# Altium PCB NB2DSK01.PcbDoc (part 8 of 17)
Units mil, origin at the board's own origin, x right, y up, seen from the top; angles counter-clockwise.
Board outline 11815 x 6500.03 mil, 8 copper layers (Top Layer, MidLayer1, MidLayer2, GND, PWR, MidLayer3, MidLayer4, Bottom Layer), stack 74.62 mil thick; 798 components, 1002 nets, 3927 pads, 3182 vias.
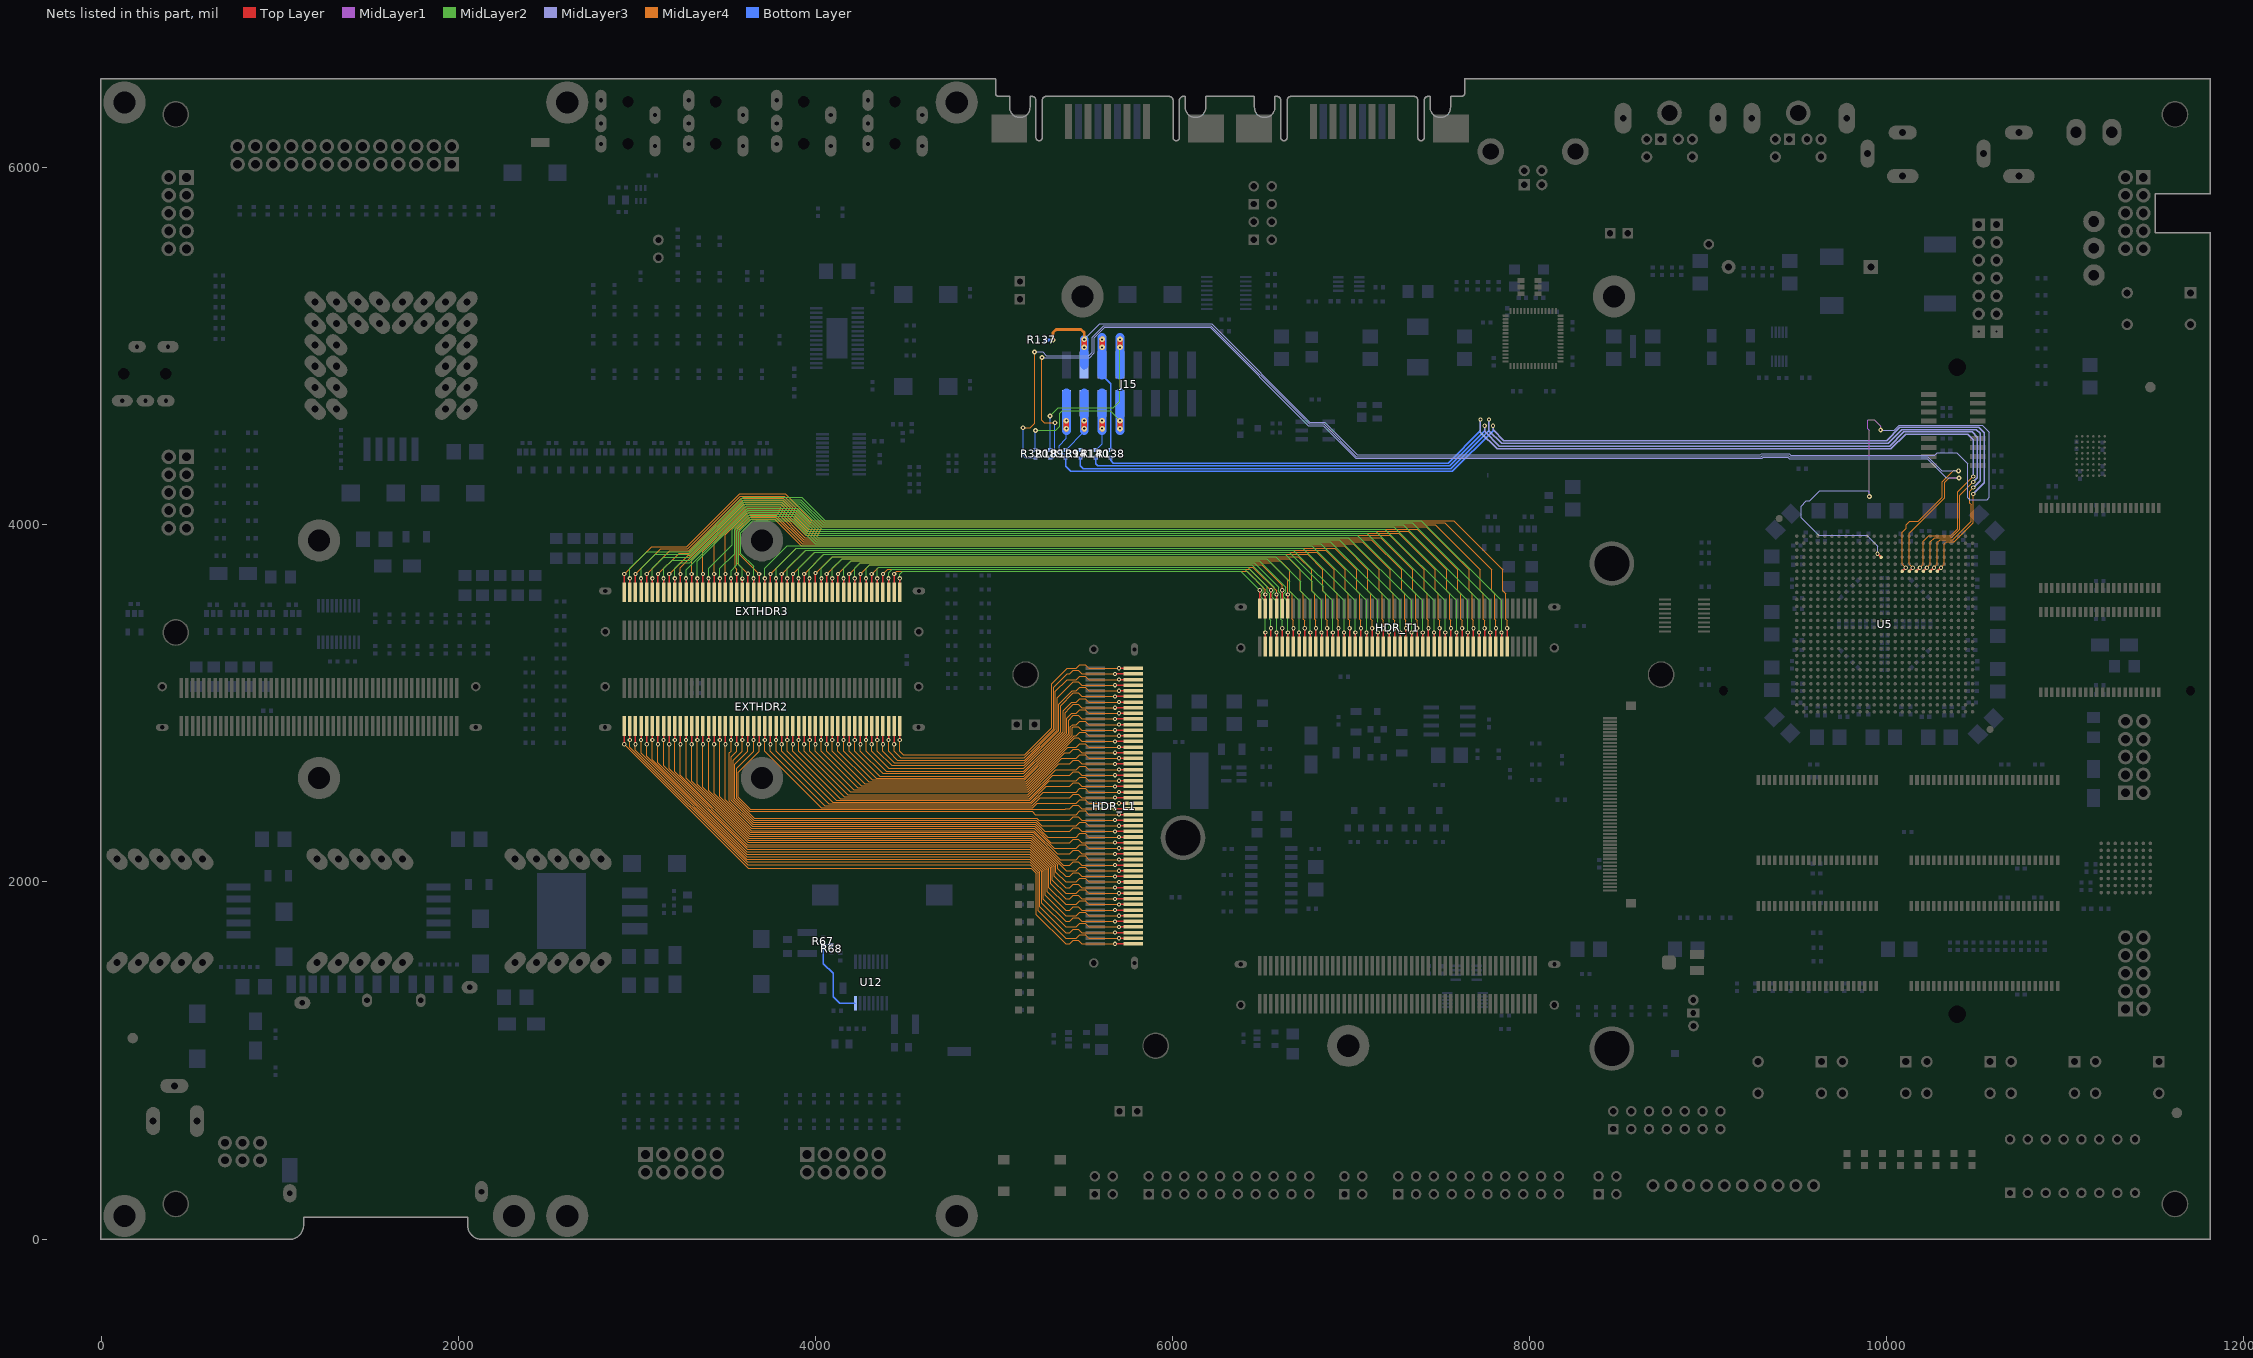
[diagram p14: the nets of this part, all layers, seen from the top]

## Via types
v1: diameter 23.62, hole 11.81, Top Layer to Bottom Layer, tented both sides, 1950 vias
v2: diameter 27.56, hole 11.81, Top Layer to Bottom Layer, tented both sides, 679 vias
v3: diameter 23.62, hole 11.81, Top Layer to Bottom Layer, 194 vias
v4: diameter 31.5, hole 11.81, Top Layer to Bottom Layer, tented both sides, 178 vias
v5: diameter 21.65, hole 11.81, Top Layer to Bottom Layer, tented both sides, 67 vias
v6: diameter 23.62, hole 11.81, Top Layer to Bottom Layer, tented bottom, 53 vias
v7: diameter 26, hole 11.81, Top Layer to Bottom Layer, tented both sides, 21 vias
v8: diameter 26, hole 11.81, Top Layer to Bottom Layer, 13 vias
v9: diameter 28, hole 11.81, Top Layer to Bottom Layer, 8 vias
v10: diameter 25.59, hole 11.81, Top Layer to Bottom Layer, tented both sides, 7 vias
v11: diameter 39.37, hole 11.81, Top Layer to Bottom Layer, tented both sides, 5 vias
v12: diameter 30, hole 11.81, Top Layer to Bottom Layer, 3 vias
v13: diameter 30, hole 11.81, Top Layer to Bottom Layer, tented both sides, 2 vias
v14: diameter 23, hole 11.81, Top Layer to Bottom Layer, tented both sides, 1 vias
v15: diameter 26.56, hole 11.81, Top Layer to Bottom Layer, tented both sides, 1 vias

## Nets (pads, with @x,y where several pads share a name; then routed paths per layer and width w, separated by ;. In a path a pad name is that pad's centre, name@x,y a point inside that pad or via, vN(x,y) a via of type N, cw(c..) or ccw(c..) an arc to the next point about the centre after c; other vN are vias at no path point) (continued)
EXT_B.D0: EXTHDR2.2 HDR_L1.2 | length 1820.1
  Top Layer w7.87: v1(4472.44,2795.28) EXTHDR2.2@4472.44,2874.02 ; v1(5700.79,3196.85) HDR_L1.2@5779.53,3196.85
  MidLayer4 w5: v1(4472.44,2795.28) 4472.44,2732.28 4493.27,2711.45 5172.08,2711.45 5323.67,2863.04 5323.67,3111.07 5409.45,3196.85 5460.63,3196.85 5480.32,3216.54 5511.81,3216.54 5531.5,3196.85 v1(5700.79,3196.85)
EXT_B.D1: EXTHDR2.4 HDR_L1.4 | length 1841.6
  Top Layer w7.87: v1(4440.95,2771.65) EXTHDR2.4@4440.95,2874.02 ; v1(5677.16,3165.36) HDR_L1.4@5779.53,3165.36
  MidLayer4 w5: v1(4440.95,2771.65) 4440.95,2732.28 4477.78,2695.45 5170.23,2695.45 5238.27,2763.5 5333.67,2858.89 5333.67,3089.57 5409.45,3165.35 5425.2,3165.35 5444.88,3185.04 5472.44,3185.04 5492.13,3165.36 v1(5677.16,3165.36)
EXT_B.D2: EXTHDR2.6 HDR_L1.6 | length 1860.7
  Top Layer w7.87: v1(4409.45,2795.28) EXTHDR2.6@4409.45,2874.02 ; v1(5700.79,3133.86) HDR_L1.6@5779.53,3133.86
  MidLayer4 w5: v1(4409.45,2795.28) 4409.45,2732.28 4459.28,2682.45 5171.37,2682.45 5343.67,2854.75 5343.67,3068.08 5409.45,3133.86 5460.63,3133.86 5480.32,3153.54 5511.81,3153.54 5531.5,3133.86 v1(5700.79,3133.86)
EXT_B.D3: EXTHDR2.8 HDR_L1.8 | length 1872.2
  Top Layer w7.87: v1(4377.95,2771.65) EXTHDR2.8@4377.95,2874.02 ; v1(5677.16,3102.36) HDR_L1.8@5779.53,3102.36
  MidLayer4 w5: v1(4377.95,2771.65) 4377.95,2732.28 4442.78,2667.45 5170.51,2667.45 5353.67,2850.61 5353.67,3030.83 5425.2,3102.36 5444.88,3122.05 5472.44,3122.05 5492.13,3102.36 v1(5677.16,3102.36)
EXT_B.D4: EXTHDR2.10 HDR_L1.10 | length 1884.8
  Top Layer w7.87: v1(4346.46,2795.28) EXTHDR2.10@4346.46,2874.02 ; v1(5700.79,3070.87) HDR_L1.10@5779.53,3070.87
  MidLayer4 w5: v1(4346.46,2795.28) 4346.46,2732.28 4426.29,2652.45 5169.65,2652.45 5268.27,2751.07 5363.67,2846.47 5363.67,2995.53 5439,3070.87 5460.63,3070.87 5480.32,3090.55 5511.81,3090.55 5531.5,3070.87 v1(5700.79,3070.87)
EXT_B.D5: EXTHDR2.12 HDR_L1.12 | length 1914.4
  Top Layer w7.87: v1(4314.96,2771.65) EXTHDR2.12@4314.96,2874.02 ; v1(5677.16,3039.37) HDR_L1.12@5779.53,3039.37
  MidLayer4 w5: v1(4314.96,2771.65) 4314.96,2732.28 4410.79,2636.45 5167.79,2636.45 5373.67,2842.33 5373.67,2987.84 5444.88,3059.06 5472.44,3059.06 5492.13,3039.37 v1(5677.16,3039.37)
EXT_B.D6: EXTHDR2.14 HDR_L1.14 | length 1929.6
  Top Layer w7.87: v1(4283.47,2795.28) EXTHDR2.14@4283.47,2874.02 ; v1(5700.79,3007.88) HDR_L1.14@5779.53,3007.88
  MidLayer4 w5: v1(4283.47,2795.28) 4283.47,2732.28 4395.3,2620.45 5165.94,2620.45 5387.81,2842.33 5387.81,2959.68 5436,3007.88 5460.63,3007.88 5480.32,3027.56 5511.81,3027.56 5531.5,3007.88 v1(5700.79,3007.88)
EXT_B.D7: EXTHDR2.16 HDR_L1.16 | length 1954.2
  Top Layer w7.87: v1(4251.97,2771.65) EXTHDR2.16@4251.97,2874.02 ; v1(5677.16,2976.38) HDR_L1.16@5779.53,2976.38
  MidLayer4 w5: v1(4251.97,2771.65) 4251.97,2732.28 4375.8,2608.45 5168.08,2608.45 5298.27,2738.64 5397.81,2838.18 5397.81,2948.99 5425.2,2976.38 5444.88,2996.06 5472.44,2996.06 5492.13,2976.38 v1(5677.16,2976.38)
EXT_B.D8: EXTHDR2.18 HDR_L1.18 | length 1969.2
  Top Layer w7.87: v1(4220.47,2795.28) EXTHDR2.18@4220.47,2874.02 ; v1(5700.79,2944.88) HDR_L1.18@5779.53,2944.88
  MidLayer4 w5: v1(4220.47,2795.28) 4220.47,2732.28 4359.3,2593.45 5167.22,2593.45 5407.81,2834.04 5407.81,2917.69 5435,2944.88 5460.63,2944.88 5480.32,2964.57 5511.81,2964.57 5531.5,2944.88 v1(5700.79,2944.88)
EXT_B.D9: EXTHDR2.20 HDR_L1.20 | length 1993.1
  Top Layer w7.87: v1(4188.98,2771.65) EXTHDR2.20@4188.98,2874.02 ; v1(5677.16,2913.39) HDR_L1.20@5779.53,2913.39
  MidLayer4 w5: v1(4188.98,2771.65) 4188.98,2732.28 4339.81,2581.45 5169.36,2581.45 5417.81,2829.9 5417.81,2906 5444.88,2933.07 5472.44,2933.07 5492.13,2913.39 v1(5677.16,2913.39)
EXT_B.D10: EXTHDR2.22 HDR_L1.22 | length 2000.4
  Top Layer w7.87: v1(4157.48,2795.28) EXTHDR2.22@4157.48,2874.02 ; v1(5700.79,2881.89) HDR_L1.22@5779.53,2881.89
  MidLayer4 w5: v1(4157.48,2795.28) 4157.48,2732.28 4318.31,2571.45 5173.51,2571.45 5328.27,2726.22 5427.81,2825.76 5427.81,2868.7 5441,2881.89 5460.63,2881.89 5480.32,2901.58 5511.81,2901.58 5531.5,2881.89 v1(5700.79,2881.89)
EXT_B.D11: EXTHDR2.24 HDR_L1.24 | length 2027.1
  Top Layer w7.87: v1(4125.99,2771.65) EXTHDR2.24@4125.98,2874.02 ; v1(5677.16,2850.4) HDR_L1.24@5779.53,2850.39
  MidLayer4 w5: v1(4125.99,2771.65) 4125.99,2732.28 4297.82,2560.45 5176.65,2560.45 5437.81,2821.62 5437.81,2863.01 5444.88,2870.08 5472.44,2870.08 5492.13,2850.4 v1(5677.16,2850.4)
EXT_B.D12: EXTHDR2.26 HDR_L1.26 | length 2030.4
  Top Layer w7.87: v1(4094.49,2795.28) EXTHDR2.26@4094.49,2874.02 ; v1(5700.79,2818.9) HDR_L1.26@5779.53,2818.9
  MidLayer4 w5: v1(4094.49,2795.28) 4094.49,2732.28 4277.32,2549.45 5179.79,2549.45 5348.27,2717.93 5449.23,2818.9 5460.63,2818.9 5480.32,2838.58 5511.81,2838.58 5531.5,2818.9 v1(5700.79,2818.9)
EXT_B.D13: EXTHDR2.28 HDR_L1.28 | length 2057.2
  Top Layer w7.87: v1(4062.99,2771.65) EXTHDR2.28@4062.99,2874.02 ; v1(5677.16,2787.4) HDR_L1.28@5779.53,2787.4
  MidLayer4 w5: v1(4062.99,2771.65) 4062.99,2732.28 4255.82,2539.45 5183.93,2539.45 5358.27,2713.79 ; 5358.27,2713.79 5451.57,2807.09 5472.44,2807.09 5492.13,2787.4 v1(5677.16,2787.4)
EXT_B.D14: EXTHDR2.30 HDR_L1.30 | length 2085.5
  Top Layer w7.87: v1(4031.5,2795.28) EXTHDR2.30@4031.5,2874.02 ; v1(5700.79,2755.91) HDR_L1.30@5779.53,2755.91
  MidLayer4 w5: v1(4031.5,2795.28) 4031.5,2732.28 4236.33,2527.45 5186.07,2527.45 5414.53,2755.91 5460.63,2755.91 5480.32,2775.59 5511.81,2775.59 5531.5,2755.91 v1(5700.79,2755.91)
EXT_B.D15: EXTHDR2.32 HDR_L1.32 | length 2113.1
  Top Layer w7.87: v1(4000,2771.65) EXTHDR2.32@4000,2874.02 ; v1(5677.16,2724.41) HDR_L1.32@5779.53,2724.41
  MidLayer4 w5: v1(4000,2771.65) 4000,2732.28 4215.83,2516.45 5189.22,2516.45 5397.17,2724.41 5425.2,2724.41 5444.88,2744.1 5472.44,2744.1 5492.13,2724.41 v1(5677.16,2724.41)
EXT_B.D16: EXTHDR2.34 HDR_L1.34 | length 2141.5
  Top Layer w7.87: v1(3968.51,2795.28) EXTHDR2.34@3968.5,2874.02 ; v1(5700.79,2692.91) HDR_L1.34@5779.53,2692.91
  MidLayer4 w5: v1(3968.51,2795.28) 3968.51,2732.28 4196.33,2504.45 5191.36,2504.45 5379.82,2692.91 5460.63,2692.91 5480.32,2712.6 5511.81,2712.6 5531.5,2692.91 v1(5700.79,2692.91)
EXT_B.D17: EXTHDR2.36 HDR_L1.36 | length 2174
  Top Layer w7.87: v1(3937.01,2771.65) EXTHDR2.36@3937.01,2874.02 ; v1(5677.16,2661.42) HDR_L1.36@5779.53,2661.42
  MidLayer4 w5: v1(3937.01,2771.65) 3937.01,2732.28 4181.81,2487.48 5188.53,2487.48 5362.47,2661.42 5425.2,2661.42 5444.88,2681.1 5472.44,2681.1 5492.13,2661.42 v1(5677.16,2661.42)
EXT_B.D18: EXTHDR2.38 HDR_L1.38 | length 2200.7
  Top Layer w7.87: v1(3905.51,2795.28) EXTHDR2.38@3905.51,2874.02 ; v1(5700.79,2629.92) HDR_L1.38@5779.53,2629.92
  MidLayer4 w5: v1(3905.51,2795.28) 3905.51,2732.28 4160.32,2477.48 5192.67,2477.48 5345.11,2629.92 5460.63,2629.92 5480.32,2649.61 5511.81,2649.61 5531.5,2629.92 v1(5700.79,2629.92)
EXT_B.D19: EXTHDR2.40 HDR_L1.40 | length 2227.5
  Top Layer w7.87: v1(3874.02,2771.65) EXTHDR2.40@3874.02,2874.02 ; v1(5677.16,2598.43) HDR_L1.40@5779.53,2598.43
  MidLayer4 w5: v1(3874.02,2771.65) 3874.02,2732.28 4138.82,2467.48 5196.81,2467.48 5327.76,2598.43 5425.2,2598.43 5444.88,2618.11 5472.44,2618.11 5492.13,2598.43 v1(5677.16,2598.43)
EXT_B.D20: EXTHDR2.42 HDR_L1.42 | length 2254.2
  Top Layer w7.87: v1(3842.52,2795.28) EXTHDR2.42@3842.52,2874.02 ; v1(5700.79,2566.93) HDR_L1.42@5779.53,2566.93
  MidLayer4 w5: v1(3842.52,2795.28) 3842.52,2732.28 4117.32,2457.48 5200.95,2457.48 5310.4,2566.93 5460.63,2566.93 5480.32,2586.61 5511.81,2586.61 5531.5,2566.93 v1(5700.79,2566.93)
EXT_B.D21: EXTHDR2.44 HDR_L1.44 | length 2280.9
  Top Layer w7.87: v1(3811.02,2771.65) EXTHDR2.44@3811.02,2874.02 ; v1(5677.16,2535.43) HDR_L1.44@5779.53,2535.43
  MidLayer4 w5: v1(3811.02,2771.65) 3811.02,2732.28 4095.83,2447.48 5205.1,2447.48 5293.05,2535.43 5425.2,2535.43 5444.88,2555.12 5472.44,2555.12 5492.13,2535.43 v1(5677.16,2535.43)
EXT_B.D22: EXTHDR2.46 HDR_L1.46 | length 2307.7
  Top Layer w7.87: v1(3779.53,2795.28) EXTHDR2.46@3779.53,2874.02 ; v1(5700.79,2503.94) HDR_L1.46@5779.53,2503.94
  MidLayer4 w5: v1(3779.53,2795.28) 3779.53,2732.28 4074.33,2437.48 5209.24,2437.48 5275.7,2503.94 5460.63,2503.94 5480.32,2523.62 5511.81,2523.62 5531.5,2503.94 v1(5700.79,2503.94)
EXT_B.D23: EXTHDR2.48 HDR_L1.48 | length 2334.4
  Top Layer w7.87: v1(3748.03,2771.65) EXTHDR2.48@3748.03,2874.02 ; v1(5677.16,2472.44) HDR_L1.48@5779.53,2472.44
  MidLayer4 w5: v1(3748.03,2771.65) 3748.03,2732.28 4052.83,2427.48 5213.38,2427.48 5258.34,2472.44 5425.2,2472.44 5444.88,2492.13 5472.44,2492.13 5492.13,2472.44 v1(5677.16,2472.44)
EXT_B.D24: EXTHDR2.50 HDR_L1.50 | length 2361.6
  Top Layer w7.87: v1(3716.54,2795.28) EXTHDR2.50@3716.54,2874.02 ; v1(5700.79,2440.95) HDR_L1.50@5779.53,2440.95
  MidLayer4 w5: v1(3716.54,2795.28) 3716.54,2732.28 4031.89,2416.93 5216.97,2416.93 5240.99,2440.95 5460.63,2440.95 5480.32,2460.63 5511.81,2460.63 5531.5,2440.95 v1(5700.79,2440.95)
EXT_B.D25: EXTHDR2.52 HDR_L1.52 | length 2704.6
  Top Layer w7.87: v1(3685.04,2771.65) EXTHDR2.52@3685.04,2874.02 ; v1(5677.16,2409.45) HDR_L1.52@5779.53,2409.45
  MidLayer4 w5: v1(3685.04,2771.65) 3685.04,2732.28 3568.74,2615.98 3568.74,2473.69 3635.81,2406.62 5398.74,2406.62 5401.58,2409.45 5425.2,2409.45 5444.88,2429.13 5472.44,2429.13 5492.13,2409.45 v1(5677.16,2409.45)
EXT_B.D26: EXTHDR2.54 HDR_L1.54 | length 2718.8
  Top Layer w7.87: v1(3653.54,2795.28) EXTHDR2.54@3653.54,2874.02 ; v1(5700.79,2377.95) HDR_L1.54@5779.53,2377.95
  MidLayer4 w5: v1(3653.54,2795.28) 3653.54,2732.28 3558.74,2637.48 3558.74,2469.55 3631.67,2396.61 5213.62,2396.61 5232.28,2377.95 5460.63,2377.95 5480.32,2397.64 5511.81,2397.64 5531.5,2377.95 v1(5700.79,2377.95)
EXT_B.D27: EXTHDR2.56 HDR_L1.56 | length 2735.3
  Top Layer w7.87: v1(3622.05,2771.65) EXTHDR2.56@3622.05,2874.02 ; v1(5677.16,2346.46) HDR_L1.56@5779.53,2346.46
  MidLayer4 w5: v1(3622.05,2771.65) 3622.05,2732.28 3548.74,2658.98 3548.74,2465.4 3656.98,2357.16 5238.93,2357.16 5249.64,2346.46 5425.2,2346.46 5444.88,2366.14 5472.44,2366.14 5492.13,2346.46 v1(5677.16,2346.46)
EXT_B.D28: EXTHDR2.58 HDR_L1.58 | length 2751.9
  Top Layer w7.87: v1(3590.55,2795.28) EXTHDR2.58@3590.55,2874.02 ; v1(5700.79,2314.96) HDR_L1.58@5779.53,2314.96
  MidLayer4 w5: v1(3590.55,2795.28) 3590.55,2732.28 3538.74,2680.47 3538.74,2461.26 3655.55,2344.45 5237.5,2344.45 5266.99,2314.96 5460.63,2314.96 5480.32,2334.65 5511.81,2334.65 5531.5,2314.96 v1(5700.79,2314.96)
EXT_B.D29: EXTHDR2.60 HDR_L1.60 | length 2768.5
  Top Layer w7.87: v1(3559.06,2771.65) EXTHDR2.60@3559.06,2874.02 ; v1(5677.16,2283.47) HDR_L1.60@5779.53,2283.47
  MidLayer4 w5: v1(3559.06,2771.65) 3559.06,2732.28 3528.74,2701.97 3528.74,2457.12 3652.4,2333.45 5234.36,2333.45 5284.35,2283.47 5425.2,2283.47 5444.88,2303.15 5472.44,2303.15 5492.13,2283.47 v1(5677.16,2283.47)
EXT_B.D30: EXTHDR2.62 HDR_L1.62 | length 2785
  Top Layer w7.09: v1(3527.56,2795.28) EXTHDR2.62@3527.56,2874.02 ; v1(5700.79,2251.97) HDR_L1.62@5779.53,2251.97
  MidLayer4 w5: v1(3527.56,2795.28) 3527.56,2732.28 3518.74,2723.46 3518.74,2452.98 3649.26,2322.45 5231.22,2322.45 5301.7,2251.97 5460.63,2251.97 5480.32,2271.65 5511.81,2271.65 5531.5,2251.97 v1(5700.79,2251.97)
EXT_B.D31: EXTHDR2.64 HDR_L1.64 | length 2812.1
  Top Layer w7.09: v1(3496.06,2771.65) EXTHDR2.64@3496.06,2874.02 ; v1(5677.16,2220.47) HDR_L1.64@5779.53,2220.47
  MidLayer4 w5: v1(3496.06,2771.65) 3496.06,2461.51 3645.12,2312.45 5227.07,2312.45 5319.05,2220.47 5425.2,2220.47 5444.88,2240.16 5472.44,2240.16 5492.13,2220.47 v1(5677.16,2220.47)
EXT_B.D32: EXTHDR2.66 HDR_L1.66 | length 2847.4
  Top Layer w7.09: v1(3464.57,2795.28) EXTHDR2.66@3464.57,2874.02 ; v1(5700.79,2188.98) HDR_L1.66@5779.53,2188.98
  MidLayer4 w5: v1(3464.57,2795.28) 3464.57,2477.26 3641.37,2300.45 5224.93,2300.45 5336.41,2188.98 5460.63,2188.98 5480.32,2208.66 5511.81,2208.66 5531.5,2188.98 v1(5700.79,2188.98)
EXT_B.D33: EXTHDR2.68 HDR_L1.68 | length 2881.8
  Top Layer w7.09: v1(3433.07,2771.65) EXTHDR2.68@3433.07,2874.02 ; v1(5677.16,2157.48) HDR_L1.68@5779.53,2157.48
  MidLayer4 w5: v1(3433.07,2771.65) 3433.07,2494.61 3639.52,2288.16 5223.08,2288.16 5353.76,2157.48 5425.2,2157.48 5444.88,2177.17 5472.44,2177.17 5492.13,2157.48 v1(5677.16,2157.48)
EXT_B.D34: EXTHDR2.70 HDR_L1.70 | length 2916.2
  Top Layer w7.09: v1(3401.58,2795.28) EXTHDR2.70@3401.57,2874.02 ; v1(5700.79,2125.99) HDR_L1.70@5779.53,2125.98
  MidLayer4 w5: v1(3401.58,2795.28) 3401.58,2511.97 3635.84,2277.71 5219.39,2277.71 5371.12,2125.99 5460.63,2125.99 5480.32,2145.67 5511.81,2145.67 5531.5,2125.99 v1(5700.79,2125.99)
EXT_B.D35: EXTHDR2.72 HDR_L1.72 | length 2950.6
  Top Layer w7.09: v1(3370.08,2771.65) EXTHDR2.72@3370.08,2874.02 ; v1(5677.16,2094.49) HDR_L1.72@5779.53,2094.49
  MidLayer4 w5: v1(3370.08,2771.65) 3370.08,2529.32 3631.94,2267.45 5215.5,2267.45 5388.47,2094.49 5425.2,2094.49 5444.88,2114.17 5472.44,2114.17 5492.13,2094.49 v1(5677.16,2094.49)
EXT_B.D36: EXTHDR2.74 HDR_L1.74 | length 2984.9
  Top Layer w7.09: v1(3338.58,2795.28) EXTHDR2.74@3338.58,2874.02 ; v1(5700.79,2062.99) HDR_L1.74@5779.53,2062.99
  MidLayer4 w5: v1(3338.58,2795.28) 3338.58,2546.67 3628.8,2256.45 5212.36,2256.45 5405.82,2062.99 5460.63,2062.99 5480.32,2082.68 5511.81,2082.68 5531.5,2062.99 v1(5700.79,2062.99)
EXT_B.D37: EXTHDR2.76 HDR_L1.76 | length 3032.5
  Top Layer w7.09: v1(3307.09,2771.65) EXTHDR2.76@3307.09,2874.02 ; v1(5677.16,2031.5) HDR_L1.76@5779.53,2031.5
  MidLayer4 w5: v1(3307.09,2771.65) 3307.09,2564.03 3625.66,2245.45 5209.22,2245.45 5357.13,2097.55 5357.13,2075.12 5400.75,2031.5 5425.2,2031.5 5444.88,2051.18 5472.44,2051.18 5492.13,2031.5 v1(5677.16,2031.5)
EXT_B.D38: EXTHDR2.78 HDR_L1.78 | length 3077
  Top Layer w7.09: v1(3275.59,2795.28) EXTHDR2.78@3275.59,2874.02 ; v1(5700.79,2000) HDR_L1.78@5779.53,2000
  MidLayer4 w5: v1(3275.59,2795.28) 3275.59,2581.38 3622.52,2234.45 5206.08,2234.45 5347.13,2093.41 5347.13,2053.62 5400.75,2000 5460.63,2000 5480.32,2019.69 5511.81,2019.69 5531.5,2000 v1(5700.79,2000)
EXT_B.D39: EXTHDR2.80 HDR_L1.80 | length 3121.5
  Top Layer w7.09: v1(3244.1,2771.65) EXTHDR2.80@3244.09,2874.02 ; v1(5677.16,1968.51) HDR_L1.80@5779.53,1968.5
  MidLayer4 w5: v1(3244.1,2771.65) 3244.09,2598.74 3620.38,2222.45 5203.94,2222.45 5337.13,2089.27 5337.13,2032.13 5400.75,1968.51 5425.2,1968.51 5444.88,1988.19 5472.44,1988.19 5492.13,1968.51 v1(5677.16,1968.51)
EXT_B.D40: EXTHDR2.82 HDR_L1.82 | length 3166.1
  Top Layer w7.09: v1(3212.6,2795.28) EXTHDR2.82@3212.6,2874.02 ; v1(5700.79,1937.01) HDR_L1.82@5779.53,1937.01
  MidLayer4 w5: v1(3212.6,2795.28) 3212.6,2616.09 3619.24,2209.45 5202.8,2209.45 5327.13,2085.12 5327.13,2010.63 5400.75,1937.01 5460.63,1937.01 5480.32,1956.69 5511.81,1956.69 5531.5,1937.01 v1(5700.79,1937.01)
EXT_B.D41: EXTHDR2.84 HDR_L1.84 | length 3210.6
  Top Layer w7.09: v1(3181.1,2771.65) EXTHDR2.84@3181.1,2874.02 ; v1(5677.16,1905.51) HDR_L1.84@5779.53,1905.51
  MidLayer4 w5: v1(3181.1,2771.65) 3181.1,2633.44 3616.09,2198.45 5199.65,2198.45 5317.13,2080.98 5317.13,1989.13 5400.75,1905.51 5425.2,1905.51 5444.88,1925.2 5472.44,1925.2 5492.13,1905.51 v1(5677.16,1905.51)
EXT_B.D42: EXTHDR2.86 HDR_L1.86 | length 3255.2
  Top Layer w7.09: v1(3149.61,2795.28) EXTHDR2.86@3149.61,2874.02 ; v1(5700.79,1874.02) HDR_L1.86@5779.53,1874.02
  MidLayer4 w5: v1(3149.61,2795.28) 3149.61,2650.8 3616.95,2183.45 5200.51,2183.45 5307.13,2076.84 5307.13,1967.64 5400.75,1874.02 5460.63,1874.02 5480.32,1893.7 5511.81,1893.7 5531.5,1874.02 v1(5700.79,1874.02)
EXT_B.D43: EXTHDR2.88 HDR_L1.88 | length 3299.7
  Top Layer w7.09: v1(3118.11,2771.65) EXTHDR2.88@3118.11,2874.02 ; v1(5677.16,1842.52) HDR_L1.88@5779.53,1842.52
  MidLayer4 w5: v1(3118.11,2771.65) 3118.11,2668.15 3615.81,2170.45 5199.37,2170.45 5297.13,2072.7 5297.13,1946.14 5400.75,1842.52 5425.2,1842.52 5444.88,1862.2 5472.44,1862.2 5492.13,1842.52 v1(5677.16,1842.52)
EXT_B.D44: EXTHDR2.90 HDR_L1.90 | length 3344.3
  Top Layer w7.87: v1(3086.61,2795.28) EXTHDR2.90@3086.61,2874.02 ; v1(5700.79,1811.02) HDR_L1.90@5779.53,1811.02
  MidLayer4 w5: v1(3086.61,2795.28) 3086.61,2685.51 3615.67,2156.45 5199.23,2156.45 5287.13,2068.55 5287.13,1924.65 5400.75,1811.02 5460.63,1811.02 5480.32,1830.71 5511.81,1830.71 5531.5,1811.02 v1(5700.79,1811.02)
EXT_B.D45: EXTHDR2.92 HDR_L1.92 | length 3388.8
  Top Layer w7.87: v1(3055.12,2771.65) EXTHDR2.92@3055.12,2874.02 ; v1(5677.16,1779.53) HDR_L1.92@5779.53,1779.53
  MidLayer4 w5: v1(3055.12,2771.65) 3055.12,2702.86 3616.52,2141.45 5200.08,2141.45 5277.13,2064.41 5277.13,1903.15 5400.75,1779.53 5425.2,1779.53 5444.88,1799.21 5472.44,1799.21 5492.13,1779.53 v1(5677.16,1779.53)
EXT_B.D46: EXTHDR2.94 HDR_L1.94 | length 3433.3
  Top Layer w7.87: v1(3023.62,2795.28) EXTHDR2.94@3023.62,2874.02 ; v1(5700.79,1748.03) HDR_L1.94@5779.53,1748.03
  MidLayer4 w5: v1(3023.62,2795.28) 3023.62,2720.22 3615.38,2128.45 5198.94,2128.45 5267.13,2060.27 5267.13,1881.65 5400.75,1748.03 5460.63,1748.03 5480.32,1767.72 5511.81,1767.72 5531.5,1748.03 v1(5700.79,1748.03)
EXT_B.D47: EXTHDR2.96 HDR_L1.96 | length 3477.9
  Top Layer w7.87: v1(2992.13,2771.65) EXTHDR2.96@2992.13,2874.02 ; v1(5677.16,1716.54) HDR_L1.96@5779.53,1716.54
  MidLayer4 w5: v1(2992.13,2771.65) 2992.12,2737.57 3617.24,2112.45 5200.8,2112.45 5257.13,2056.13 5257.13,1860.16 5400.75,1716.54 5425.2,1716.54 5444.88,1736.22 5472.44,1736.22 5492.13,1716.54 v1(5677.16,1716.54)
EXT_B.D48: EXTHDR2.98 HDR_L1.98 | length 3522.4
  Top Layer w7.87: v1(2960.63,2795.28) EXTHDR2.98@2960.63,2874.02 ; v1(5700.79,1685.04) HDR_L1.98@5779.53,1685.04
  MidLayer4 w5: v1(2960.63,2795.28) 2960.63,2754.92 3620.1,2095.45 5203.66,2095.45 5247.13,2051.99 5247.13,1838.66 5400.75,1685.04 5460.63,1685.04 5480.32,1704.72 5511.81,1704.72 5531.5,1685.04 v1(5700.79,1685.04)
EXT_B.D49: EXTHDR2.100 HDR_L1.100 | length 3568.2
  Top Layer w7.87: v1(2929.13,2771.65) EXTHDR2.100@2929.13,2874.02 ; v1(5677.16,1653.54) HDR_L1.100@5779.53,1653.54
  MidLayer4 w5: v1(2929.13,2771.65) 2929.13,2772.28 2929.44,2771.97 3624.96,2076.45 5208.52,2076.45 5237.13,2047.84 5237.13,1817.17 5400.75,1653.54 5425.2,1653.54 5444.88,1673.23 5472.44,1673.23 5492.13,1653.54 v1(5677.16,1653.54)
EXT_C.D0: EXTHDR3.2 HDR_T1.89 | length 5824.6
  Top Layer w7.87: EXTHDR3.2@2929.13,3622.05 v1(2929.13,3724.41) ; HDR_T1.89@7874.02,3318.9 v1(7874.02,3421.26)
  MidLayer4 w5: v1(2929.13,3724.41) 3082.68,3877.95 3279.87,3877.95 3326.1,3924.18 3441.97,4040.05 3575.15,4173.23 3830.36,4173.23 3979.97,4023.62 4590.55,4023.62 7574.8,4023.62 7850.4,3748.03 7850.4,3629.92 7866.14,3614.17 7866.14,3472.44 7874.02,3464.57 v1(7874.02,3421.26)
EXT_C.D1: EXTHDR3.4 HDR_T1.87 | length 5676.1
  Top Layer w7.87: EXTHDR3.4@2960.63,3622.05 v1(2960.63,3700.79) ; HDR_T1.87@7842.52,3318.9 v1(7842.52,3397.64)
  MidLayer2 w5: v1(2960.63,3700.79) 2960.63,3755.91 3055.12,3850.39 3292.64,3850.39 3595.79,4153.54 3923.89,4153.54 4053.81,4023.62 7393.7,4023.62 7842.52,3574.8 v1(7842.52,3397.64)
EXT_C.D2: EXTHDR3.6 HDR_T1.85 | length 5688.8
  Top Layer w7.87: EXTHDR3.6@2992.13,3622.05 v1(2992.12,3724.41) ; HDR_T1.85@7811.02,3318.9 v1(7811.02,3421.26)
  MidLayer4 w5: v1(2992.12,3724.41) 3133.86,3866.14 3284.77,3866.14 3580.04,4161.42 3825.47,4161.42 3975.08,4011.81 7523.62,4011.81 7787.4,3748.03 7787.4,3629.92 7803.15,3614.17 7803.15,3472.44 7811.03,3464.57 v1(7811.02,3421.26)
EXT_C.D3: EXTHDR3.8 HDR_T1.83 | length 5540.3
  Top Layer w7.87: EXTHDR3.8@3023.62,3622.05 v1(3023.62,3700.79) ; HDR_T1.83@7779.53,3318.9 v1(7779.53,3397.64)
  MidLayer2 w5: v1(3023.62,3700.79) 3023.62,3755.91 3102.36,3834.65 3293.6,3834.65 3600.68,4141.73 3919,4141.73 4048.92,4011.81 7342.52,4011.81 7779.53,3574.8 v1(7779.53,3397.64)
EXT_C.D4: EXTHDR3.10 HDR_T1.81 | length 5553
  Top Layer w7.87: EXTHDR3.10@3055.12,3622.05 v1(3055.12,3724.41) ; HDR_T1.81@7748.03,3318.9 v1(7748.03,3421.26)
  MidLayer4 w5: v1(3055.12,3724.41) 3185.04,3854.33 3289.66,3854.33 3584.94,4149.61 3820.58,4149.61 3970.18,4000 6196.85,4000 7472.44,4000 7724.41,3748.03 7724.41,3629.92 7740.16,3614.17 7740.16,3472.44 7748.03,3464.57 v1(7748.03,3421.26)
EXT_C.D5: EXTHDR3.12 HDR_T1.79 | length 5404.5
  Top Layer w7.87: EXTHDR3.12@3086.61,3622.05 v1(3086.61,3700.79) ; HDR_T1.79@7716.54,3318.9 v1(7716.54,3397.64)
  MidLayer2 w5: v1(3086.61,3700.79) 3086.61,3755.91 3149.61,3818.9 3294.55,3818.9 3605.58,4129.92 3914.11,4129.92 4044.03,4000 7291.34,4000 7716.54,3574.8 v1(7716.54,3397.64)
EXT_C.D6: EXTHDR3.14 HDR_T1.77 | length 5417.3
  Top Layer w7.09: EXTHDR3.14@3118.11,3622.05 v1(3118.11,3724.41)
  Top Layer w7.87: HDR_T1.77@7685.04,3318.9 v1(7685.04,3421.26)
  MidLayer4 w5: v1(3118.11,3724.41) 3236.22,3842.52 3294.55,3842.52 3589.83,4137.8 3815.68,4137.8 3965.29,3988.19 4590.55,3988.19 7421.26,3988.19 7661.42,3748.03 7661.42,3629.92 7677.17,3614.17 7677.17,3472.44 7685.04,3464.57 v1(7685.04,3421.26)
EXT_C.D7: EXTHDR3.16 HDR_T1.75 | length 5268.8
  Top Layer w7.09: EXTHDR3.16@3149.61,3622.05 v1(3149.6,3700.79)
  Top Layer w7.87: HDR_T1.75@7653.54,3318.9 v1(7653.55,3397.64)
  MidLayer2 w5: v1(3149.6,3700.79) 3149.61,3755.91 3196.85,3803.15 3295.51,3803.15 3610.47,4118.11 3909.22,4118.11 4039.14,3988.19 7240.16,3988.19 7653.55,3574.8 v1(7653.55,3397.64)
EXT_C.D8: EXTHDR3.18 HDR_T1.73 | length 5289.4
  Top Layer w7.09: EXTHDR3.18@3181.1,3622.05 v1(3181.1,3724.41)
  Top Layer w7.87: HDR_T1.73@7622.05,3318.9 v1(7622.05,3421.26)
  MidLayer4 w5: v1(3181.1,3724.41) 3287.4,3830.71 3299.45,3830.71 3594.72,4125.98 3810.79,4125.98 3960.4,3976.38 6204.72,3976.38 ; 6196.85,3976.38 6204.72,3976.38 ; v1(7622.05,3421.26) 7622.05,3464.57 7614.18,3472.44 7614.18,3614.17 7598.43,3629.92 7598.43,3748.03 7370.08,3976.38 6204.72,3976.38
EXT_C.D9: EXTHDR3.20 HDR_T1.71 | length 5133
  Top Layer w7.09: EXTHDR3.20@3212.6,3622.05 v1(3212.6,3700.79)
  Top Layer w7.87: HDR_T1.71@7590.55,3318.9 v1(7590.55,3397.64)
  MidLayer2 w5: v1(3212.6,3700.79) 3212.6,3755.91 3244.1,3787.4 3296.46,3787.4 3508.52,3999.46 3615.36,4106.3 3904.32,4106.3 4034.25,3976.38 7188.98,3976.38 7590.55,3574.8 v1(7590.55,3397.64)
EXT_C.D10: EXTHDR3.22 HDR_T1.69 | length 5169.7
  Top Layer w7.09: EXTHDR3.22@3244.09,3622.05 v1(3244.09,3724.41)
  Top Layer w7.87: HDR_T1.69@7559.06,3318.9 v1(7559.06,3421.26)
  MidLayer4 w5: v1(3244.09,3724.41) 3244.09,3758.66 3599.61,4114.18 3805.9,4114.18 3955.51,3964.57 4590.55,3964.57 ; 4586.62,3964.57 7318.9,3964.57 7535.44,3748.03 7535.44,3629.92 7551.18,3614.17 7551.18,3472.44 7559.06,3464.57 v1(7559.06,3421.26)
EXT_C.D11: EXTHDR3.24 HDR_T1.67 | length 4993.7
  Top Layer w7.09: EXTHDR3.24@3275.59,3622.05 v1(3275.59,3700.79)
  Top Layer w7.87: HDR_T1.67@7527.56,3318.9 v1(7527.56,3397.64)
  MidLayer2 w5: v1(3275.59,3700.79) 3275.59,3749.83 3620.25,4094.49 3899.43,4094.49 4029.35,3964.57 7137.8,3964.57 7527.56,3574.8 v1(7527.56,3397.64)
EXT_C.D12: EXTHDR3.26 HDR_T1.65 | length 5065
  Top Layer w7.09: EXTHDR3.26@3307.09,3622.05 v1(3307.09,3724.41)
  Top Layer w7.87: HDR_T1.65@7496.06,3318.9 v1(7496.06,3421.26)
  MidLayer4 w5: v1(3307.09,3724.41) 3307.09,3804.94 3604.5,4102.36 3801.01,4102.36 3950.61,3952.76 6204.72,3952.76 ; 6196.85,3952.76 6204.72,3952.76 ; v1(7496.06,3421.26) 7496.07,3464.57 7488.19,3472.44 7488.19,3614.17 7472.44,3629.92 7472.44,3748.03 7267.72,3952.76 6204.72,3952.76
EXT_C.D13: EXTHDR3.28 HDR_T1.63 | length 4885
  Top Layer w7.09: EXTHDR3.28@3338.58,3622.05 v1(3338.58,3700.79)
  Top Layer w7.87: HDR_T1.63@7464.57,3318.9 v1(7464.57,3397.64)
  MidLayer2 w5: v1(3338.58,3700.79) 3338.58,3796.12 3625.15,4082.68 3894.54,4082.68 4024.46,3952.76 7086.61,3952.76 7464.57,3574.8 v1(7464.57,3397.64)
EXT_C.D14: EXTHDR3.30 HDR_T1.61 | length 4952.4
  Top Layer w7.09: EXTHDR3.30@3370.08,3622.05 v1(3370.08,3724.41)
  Top Layer w7.87: HDR_T1.61@7433.07,3318.9 v1(7433.07,3421.26)
  MidLayer4 w5: v1(3370.08,3724.41) 3370.08,3851.23 3538.8,4019.96 3609.4,4090.55 3796.12,4090.55 3945.72,3940.95 4586.61,3940.95 ; 4590.55,3940.95 4586.61,3940.95 ; v1(7433.07,3421.26) 7433.07,3464.57 7425.2,3472.44 7425.2,3614.17 7409.45,3629.92 7409.45,3748.03 7216.53,3940.95 4586.62,3940.95
EXT_C.D15: EXTHDR3.32 HDR_T1.59 | length 4776.4
  Top Layer w7.09: EXTHDR3.32@3401.57,3622.05 v1(3401.57,3700.79)
  Top Layer w7.87: HDR_T1.59@7401.58,3318.9 v1(7401.58,3397.64)
  MidLayer2 w5: v1(3401.57,3700.79) 3401.58,3755.91 3535.43,3889.76 3535.43,3976.26 3630.04,4070.87 3889.65,4070.87 4019.57,3940.95 7035.43,3940.95 7401.58,3574.8 v1(7401.58,3397.64)
EXT_C.D16: EXTHDR3.34 HDR_T1.57 | length 4839.8
  Top Layer w7.09: EXTHDR3.34@3433.07,3622.05 v1(3433.07,3724.41)
  Top Layer w7.87: HDR_T1.57@7370.08,3318.9 v1(7370.08,3421.26)
  MidLayer4 w5: v1(3433.07,3724.41) 3433.07,3897.52 3542.23,4006.68 3614.29,4078.74 3791.22,4078.74 3940.83,3929.13 6196.85,3929.14 7165.35,3929.13 7346.46,3748.03 7346.46,3629.92 7362.21,3614.17 7362.21,3472.44 7370.08,3464.57 v1(7370.08,3421.26)
EXT_C.D17: EXTHDR3.36 HDR_T1.55 | length 4667.7
  Top Layer w7.09: EXTHDR3.36@3464.57,3622.05 v1(3464.57,3700.79)
  Top Layer w7.87: HDR_T1.55@7338.58,3318.9 v1(7338.58,3397.64)
  MidLayer2 w5: v1(3464.57,3700.79) 3464.57,3755.91 3547.24,3838.58 3547.24,3971.37 3634.93,4059.06 3884.76,4059.06 4014.68,3929.13 6984.25,3929.13 7338.58,3574.8 v1(7338.58,3397.64)
EXT_C.D18: EXTHDR3.38 HDR_T1.53 | length 4731.2
  Top Layer w7.09: EXTHDR3.38@3496.06,3622.05 v1(3496.06,3724.41)
  Top Layer w7.87: HDR_T1.53@7307.09,3318.9 v1(7307.09,3421.26)
  MidLayer4 w5: v1(3496.06,3724.41) 3496.06,3943.81 3619.18,4066.93 3786.33,4066.93 3935.94,3917.32 4590.55,3917.33 7114.17,3917.32 7283.47,3748.03 7283.47,3629.92 7299.21,3614.17 7299.21,3472.44 7307.09,3464.57 v1(7307.09,3421.26)
EXT_C.D19: EXTHDR3.40 HDR_T1.51 | length 4559.1
  Top Layer w7.09: EXTHDR3.40@3527.56,3622.05 v1(3527.56,3700.79)
  Top Layer w7.87: HDR_T1.51@7275.59,3318.9 v1(7275.59,3397.64)
  MidLayer2 w5: v1(3527.56,3700.79) 3527.56,3744.1 3559.06,3775.59 3559.06,3966.48 3639.82,4047.24 3879.86,4047.24 4009.78,3917.32 6933.07,3917.32 7275.59,3574.8 v1(7275.59,3397.64)
EXT_C.D20: EXTHDR3.42 HDR_T1.49 | length 4629
  Top Layer w7.87: EXTHDR3.42@3559.06,3622.05 v1(3559.05,3724.41) ; HDR_T1.49@7244.09,3318.9 v1(7244.09,3421.26)
  MidLayer4 w5: v1(3559.05,3724.41) 3559.05,3751.97 3551.18,3759.84 3551.18,3982.23 3624.07,4055.12 3781.44,4055.12 3931.04,3905.51 6196.85,3905.51 7062.99,3905.51 7220.47,3748.03 7220.47,3629.92 7236.22,3614.17 7236.22,3472.44 7244.1,3464.57 v1(7244.09,3421.26)
EXT_C.D21: EXTHDR3.44 HDR_T1.47 | length 4464.8
  Top Layer w7.87: EXTHDR3.44@3590.55,3622.05 v1(3590.55,3698.82) ; HDR_T1.47@7212.6,3318.9 v1(7212.6,3397.64)
  MidLayer2 w5: v1@3590.55,3700.79 3590.55,3755.91 3570.87,3775.59 3570.87,3961.59 3644.71,4035.43 3874.97,4035.43 4004.89,3905.51 6881.89,3905.51 7212.6,3574.8 v1(7212.6,3397.64)
EXT_C.D22: EXTHDR3.46 HDR_T1.45 | length 4560.8
  Top Layer w7.87: EXTHDR3.46@3622.05,3622.05 v1@3622.05,3724.41 ; HDR_T1.45@7181.1,3318.9 v1(7181.1,3421.26)
  MidLayer4 w5: v1(3622.05,3726.38) 3562.99,3785.44 3562.99,3977.33 3628.97,4043.31 3776.55,4043.31 3926.15,3893.7 4590.55,3893.7 7011.81,3893.7 7157.48,3748.03 7157.48,3629.92 7173.23,3614.17 7173.23,3472.44 7181.1,3464.57 v1(7181.1,3421.26)
EXT_C.D23: EXTHDR3.48 HDR_T1.43 | length 4400.5
  Top Layer w7.87: EXTHDR3.48@3653.54,3622.05 v1(3653.54,3700.79) ; HDR_T1.43@7149.61,3318.9 v1(7149.61,3397.64)
  MidLayer2 w5: v1(3653.54,3700.79) 3653.54,3767.72 3582.68,3838.58 3582.68,3956.69 3649.61,4023.62 3870.08,4023.62 4000,3893.7 6830.71,3893.7 7149.61,3574.8 v1(7149.61,3397.64)
EXT_C.D24: EXTHDR3.50 HDR_T1.41 | length 4496.5
  Top Layer w7.87: EXTHDR3.50@3685.04,3622.05 v1(3685.04,3724.41) ; HDR_T1.41@7118.11,3318.9 v1(7118.11,3421.26)
  MidLayer4 w5: v1(3685.04,3724.41) 3574.8,3834.64 3574.8,3972.44 3633.86,4031.5 3771.65,4031.5 3921.26,3881.89 6196.85,3881.89 6960.63,3881.89 7094.49,3748.03 7094.49,3629.92 7110.24,3614.17 7110.24,3472.44 7118.11,3464.57 v1(7118.11,3421.26)
EXT_C.D25: EXTHDR3.52 HDR_T1.39 | length 3939.2
  Top Layer w7.09: HDR_T1.39@7086.61,3318.9 v1(7086.62,3397.64)
  Top Layer w7.87: EXTHDR3.52@3716.54,3622.05 v1(3716.53,3700.79)
  MidLayer2 w5: v1(3716.53,3700.79) 3716.54,3755.91 3842.52,3881.89 6779.53,3881.89 7086.62,3574.8 v1(7086.62,3397.64)
EXT_C.D26: EXTHDR3.54 HDR_T1.37 | length 3935.6
  Top Layer w7.09: HDR_T1.37@7055.12,3318.9 v1(7055.12,3421.26)
  Top Layer w7.87: EXTHDR3.54@3748.03,3622.05 v1(3748.03,3724.41)
  MidLayer4 w5: v1(3748.03,3724.41) 3893.7,3870.08 4459.96,3870.08 6909.45,3870.08 7031.5,3748.03 7031.5,3629.92 7047.25,3614.17 7047.25,3472.44 7055.12,3464.57 v1(7055.12,3421.26)
EXT_C.D27: EXTHDR3.56 HDR_T1.35 | length 3803.5
  Top Layer w7.09: HDR_T1.35@7023.62,3318.9 v1(7023.62,3397.64)
  Top Layer w7.87: EXTHDR3.56@3779.53,3622.05 v1(3779.53,3700.79)
  MidLayer2 w5: v1(3779.53,3700.79) 3779.53,3755.91 3893.7,3870.08 6728.35,3870.08 7023.62,3574.8 v1(7023.62,3397.64)
EXT_C.D28: EXTHDR3.58 HDR_T1.33 | length 3803.8
  Top Layer w7.09: HDR_T1.33@6992.13,3318.9 v1(6992.13,3421.26)
  Top Layer w7.87: EXTHDR3.58@3811.02,3622.05 v1(3811.02,3724.41)
  MidLayer4 w5: v1(3811.02,3724.41) 3944.88,3858.27 6200.79,3858.27 ; 6196.85,3858.27 6200.79,3858.27 ; v1(6992.13,3421.26) 6992.13,3464.57 6984.25,3472.44 6984.25,3614.17 6968.51,3629.92 6968.51,3748.03 6858.27,3858.27 6200.79,3858.27
EXT_C.D29: EXTHDR3.60 HDR_T1.31 | length 3667.7
  Top Layer w7.09: HDR_T1.31@6960.63,3318.9 v1(6960.63,3397.64)
  Top Layer w7.87: EXTHDR3.60@3842.52,3622.05 v1(3842.52,3700.79)
  MidLayer2 w5: v1(3842.52,3700.79) 3842.52,3755.91 3944.88,3858.27 6677.17,3858.27 6960.63,3574.8 v1(6960.63,3397.64)
EXT_C.D30: EXTHDR3.62 HDR_T1.29 | length 3664.1
  Top Layer w7.09: HDR_T1.29@6929.13,3318.9 v1(6929.13,3421.26)
  Top Layer w7.87: EXTHDR3.62@3874.02,3622.05 v1(3874.02,3724.41)
  MidLayer4 w5: v1(3874.02,3724.41) 3996.06,3846.46 4590.55,3846.46 6807.08,3846.46 6905.51,3748.03 6905.51,3629.92 6921.26,3614.17 6921.26,3472.44 6929.14,3464.57 v1(6929.13,3421.26)
EXT_C.D31: EXTHDR3.64 HDR_T1.27 | length 3548.1
  Top Layer w7.09: HDR_T1.27@6897.64,3318.9 v1(6897.64,3397.64)
  Top Layer w7.87: EXTHDR3.64@3905.51,3622.05 v1(3905.51,3700.79)
  MidLayer2 w5: v1(3905.51,3700.79) 3905.51,3755.91 3996.06,3846.46 6653.54,3846.46 6844.95,3655.05 6844.95,3627.57 6897.64,3574.88 v1(6897.64,3397.64)
EXT_C.D32: EXTHDR3.66 HDR_T1.25 | length 3737
  Top Layer w7.09: HDR_T1.25@6866.14,3318.9 v1(6866.14,3421.26)
  Top Layer w7.87: EXTHDR3.66@3937.01,3622.05 v1(3937.01,3724.41)
  MidLayer4 w5: v1(3937.01,3724.41) 4047.24,3834.65 6405.51,3834.65 ; 6196.85,3834.65 6405.51,3834.65 ; v1(6866.14,3421.26) 6866.14,3464.57 6858.27,3472.44 6858.27,3614.17 6842.52,3629.92 6842.52,3748.03 6755.9,3834.65 6405.51,3834.65
EXT_C.D33: EXTHDR3.68 HDR_T1.23 | length 3430.1
  Top Layer w7.09: HDR_T1.23@6834.65,3318.9 v1(6834.65,3397.64)
  Top Layer w7.87: EXTHDR3.68@3966.54,3622.05 v1(3966.54,3700.79)
  MidLayer2 w5: v1@3964.57,3700.79 3964.57,3751.97 4047.25,3834.65 6629.92,3834.65 6782.14,3682.43 6782.14,3627.34 6834.65,3574.83 v1(6834.65,3397.64)
EXT_C.D34: EXTHDR3.70 HDR_T1.21 | length 3440.7
  Top Layer w7.09: HDR_T1.21@6803.15,3318.9 v1(6803.15,3421.26)
  Top Layer w7.87: EXTHDR3.70@4000,3622.05 v1@4000,3728.35
  MidLayer4 w5: v1@4000.98,3729.33 4094.49,3822.84 4590.55,3822.84 ; 4543.31,3822.84 6704.72,3822.84 6779.53,3748.03 6779.53,3629.92 6795.28,3614.17 6795.28,3472.44 6803.15,3464.57 v1(6803.15,3421.26)
  other v1: 4000,3730.32
EXT_C.D35: EXTHDR3.72 HDR_T1.19 | length 3291.9
  Top Layer w7.09: HDR_T1.19@6771.65,3318.9 v1(6771.65,3397.64)
  Top Layer w7.87: EXTHDR3.72@4033.47,3622.05 v1(4033.46,3700.79)
  MidLayer2 w5: v1(4033.46,3700.79) 4033.46,3757.87 4098.43,3822.83 6578.74,3822.84 6718.88,3682.69 6718.88,3627.56 6771.65,3574.79 v1(6771.65,3397.64)
EXT_C.D36: EXTHDR3.74 HDR_T1.17 | length 3563.9
  Top Layer w7.09: HDR_T1.17@6740.16,3318.9 v1(6740.16,3421.26)
  Top Layer w7.87: EXTHDR3.74@4062.99,3622.05 v1(4062.99,3724.41)
  MidLayer4 w5: v1(4062.99,3724.41) 4149.61,3811.02 6503.94,3811.03 ; 6196.85,3811.03 6503.94,3811.03 ; v1(6740.16,3421.26) 6740.16,3464.57 6732.28,3472.44 6732.28,3614.17 6716.54,3629.92 6716.54,3748.03 6653.54,3811.03 6503.94,3811.03
EXT_C.D37: EXTHDR3.76 HDR_T1.15 | length 3156.9
  Top Layer w7.09: HDR_T1.15@6708.66,3318.9 v1(6708.66,3397.64)
  Top Layer w7.87: EXTHDR3.76@4094.49,3622.05 v1(4094.49,3700.79)
  MidLayer2 w5: v1(4094.49,3700.79) 4094.49,3755.91 4149.61,3811.02 6527.56,3811.02 6656.24,3682.35 6656.24,3627.16 6708.66,3574.74 v1(6708.66,3397.64)
EXT_C.D38: EXTHDR3.78 HDR_T1.13 | length 3188
  Top Layer w7.09: HDR_T1.13@6677.16,3318.9 v1(6677.16,3421.26)
  Top Layer w7.87: EXTHDR3.78@4125.98,3622.05 v1(4125.98,3724.41)
  MidLayer4 w5: v1(4125.98,3724.41) 4200.79,3799.21 4590.55,3799.22 ; 4523.62,3799.21 6602.36,3799.21 6657.02,3744.55 6657.02,3626.38 6669.29,3614.11 6669.29,3472.44 6677.17,3464.57 v1(6677.16,3421.26)
EXT_C.D39: EXTHDR3.80 HDR_T1.11 | length 3035.5
  Top Layer w7.87: EXTHDR3.80@4157.48,3622.05 v1(4157.48,3700.79) ; HDR_T1.11@6645.67,3318.9 v1(6645.67,3397.64)
  MidLayer2 w5: v1(4157.48,3700.79) 4157.48,3755.91 4200.79,3799.21 6484.25,3799.21 6633.86,3649.61 6633.86,3625.99 6622.05,3614.17 6622.05,3594.49 6645.67,3570.87 v1(6645.67,3397.64)
EXT_C.D40: EXTHDR3.82 HDR_T1.12 | length 2785.7
  Top Layer w7.87: EXTHDR3.82@4188.98,3622.05 v1(4188.98,3724.41) ; HDR_T1.12@6645.67,3531.5 v1(6645.67,3610.24)
  MidLayer4 w5: v1(4188.98,3724.41) 4251.97,3787.4 6551.18,3787.4 6645.67,3692.91 v1(6645.67,3610.24)
EXT_C.D41: EXTHDR3.84 HDR_T1.9 | length 2916.9
  Top Layer w7.87: EXTHDR3.84@4220.47,3622.05 v1(4220.47,3700.79) ; HDR_T1.9@6614.17,3318.9 v1(6614.17,3421.26)
  MidLayer2 w5: v1(4220.47,3700.79) 4220.47,3755.91 4251.97,3787.4 ; 4251.97,3787.4 6456.69,3787.4 6593.85,3650.24 6593.85,3626.62 6606.3,3614.17 6606.3,3472.44 6614.17,3464.57 v1(6614.17,3421.26)
EXT_C.D42: EXTHDR3.86 HDR_T1.10 | length 2663
  Top Layer w7.87: EXTHDR3.86@4251.97,3622.05 v1(4251.97,3724.41) ; HDR_T1.10@6614.17,3531.5 v1(6614.17,3633.86)
  MidLayer4 w5: v1(4251.97,3724.41) 4303.15,3775.59 6500,3775.59 6614.17,3661.42 v1(6614.17,3633.86)
EXT_C.D43: EXTHDR3.88 HDR_T1.7 | length 2827
  Top Layer w7.87: EXTHDR3.88@4283.47,3622.05 v1(4283.46,3700.79) ; HDR_T1.7@6582.68,3318.9 v1(6582.68,3397.64)
  MidLayer2 w5: v1(4283.46,3700.79) 4283.47,3755.91 4303.15,3775.59 6444.88,3775.59 6570.87,3649.61 6570.87,3625.99 6559.06,3614.17 6559.06,3594.49 6582.68,3570.87 v1(6582.68,3397.64)
EXT_C.D44: EXTHDR3.90 HDR_T1.8 | length 2540.3
  Top Layer w7.87: EXTHDR3.90@4314.96,3622.05 v1(4314.96,3724.41) ; HDR_T1.8@6582.68,3531.5 v1(6582.68,3610.24)
  MidLayer4 w5: v1(4314.96,3724.41) 4354.33,3763.78 6448.82,3763.78 6582.68,3629.92 v1(6582.68,3610.24)
EXT_C.D45: EXTHDR3.92 HDR_T1.5 | length 2710.6
  Top Layer w7.87: EXTHDR3.92@4346.46,3622.05 v1(4346.46,3700.79) ; HDR_T1.5@6551.18,3318.9 v1(6551.18,3421.26)
  MidLayer2 w5: v1(4346.46,3700.79) 4346.46,3755.91 4354.33,3763.78 6421.26,3763.78 6531.5,3653.54 6531.5,3625.98 6543.31,3614.17 6543.31,3472.44 6551.18,3464.57 v1(6551.18,3421.26)
EXT_C.D46: EXTHDR3.94 HDR_T1.6 | length 2438.3
  Top Layer w7.87: EXTHDR3.94@4377.95,3622.05 v1(4377.95,3724.41) ; HDR_T1.6@6551.18,3531.5 v1(6551.18,3633.86)
  MidLayer4 w5: v1(4377.95,3724.41) 4405.51,3751.97 6433.07,3751.97 v1(6551.18,3633.86)
EXT_C.D47: EXTHDR3.96 HDR_T1.3 | length 2604.6
  Top Layer w7.87: EXTHDR3.96@4409.45,3622.05 v1(4409.45,3700.79) ; HDR_T1.3@6519.68,3318.9 v1(6519.69,3397.64)
  MidLayer2 w5: v1(4409.45,3700.79) 4409.45,3732.28 4429.13,3751.97 6405.51,3751.97 6507.87,3649.61 6507.87,3625.99 6496.06,3614.17 6496.06,3594.49 6519.68,3570.87 v1(6519.69,3397.64)
EXT_C.D48: EXTHDR3.98 HDR_T1.4 | length 2336.3
  Top Layer w7.87: EXTHDR3.98@4440.95,3622.05 v1(4440.94,3724.41) ; HDR_T1.4@6519.68,3531.5 v1(6519.68,3610.24)
  MidLayer4 w5: v1(4440.94,3724.41) 4456.69,3740.16 6417.32,3740.16 6519.68,3637.8 v1(6519.68,3610.24)
EXT_C.D49: EXTHDR3.100 HDR_T1.2 | length 2271
  Top Layer w7.87: EXTHDR3.100@4472.44,3622.05 v1(4472.44,3700.79) ; HDR_T1.2@6488.19,3531.5 v1(6488.19,3633.86)
  MidLayer2 w5: v1(4472.44,3700.79) 4472.44,3724.41 4488.19,3740.16 6381.89,3740.16 v1(6488.19,3633.86)
EXTCTRL#.1WIRE: J15.14 R137.1 U5.D13 | length 8938.4
  Top Layer w7.87: v1(9948.82,3838.58) U5.D13@9968.5,3818.9
  Top Layer w30: v4(5505.51,4994.27) v4(5505.51,5039.19)
  MidLayer1 w5: v9(9902,4158.5) 9902,4530 9893,4539 9893,4585 9896.94,4588.94 9929.05,4588.94 9965.7,4552.29 v8(9965.7,4531.1)
  MidLayer1 w30: v4(5505.51,4994.27) v4(5505.51,5039.19)
  MidLayer2 w30: v4(5505.51,4994.27) v4(5505.51,5039.19)
  MidLayer4 w15.75: v2(5331.21,5035.42) 5331.21,5076.81 5348.9,5094.5 5488.1,5094.5 5505.51,5077.09 v4(5505.51,5039.19)
  MidLayer4 w30: v4(5505.51,4994.27) v4(5505.51,5039.19)
  MidLayer3 w5: v4(5505.51,5039.19) 5592.32,5126 6218.8,5126 6769.3,4575.5 6851.31,4575.5 7034.31,4392.5 9292.5,4392.5 9298.5,4398.5 9452.84,4398.5 9460.88,4390.45 10268.05,4390.45 10282.1,4404.5 10392.3,4404.5 10454.3,4342.5 10454.3,4153.3 10466.1,4141.5 10561.5,4141.5 10574.6,4154.6 10574.6,4517.7 10534.37,4557.93 10069.32,4557.93 10042.48,4531.1 v8(9965.7,4531.1) ; v9(9902,4158.5) 9902,4181.4 9892.95,4190.45 9623.73,4190.45 9568.08,4134.8 9549.6,4134.8 9520.3,4105.5 9520.3,4038.97 9617.69,3941.58 9887.54,3941.58 9948.82,3880.3 v1(9948.82,3838.58)
  MidLayer3 w30: v4(5505.51,4994.27) v4(5505.51,5039.19)
  Bottom Layer w15.75: R137.1@5288.89,5035.42 v2(5331.21,5035.42)
  Bottom Layer w50: J15.14@5505.51,4896.09 v4(5505.51,5039.19)
EXTCTRL#.CS1_N: J15.11 R140.1 | length 558.9
  Top Layer w30: v4(5605.51,4538.77) v4(5605.51,4583.68)
  MidLayer1 w30: v4(5605.51,4538.77) v4(5605.51,4583.68)
  MidLayer2 w30: v4(5605.51,4538.77) v4(5605.51,4583.68)
  MidLayer4 w30: v4(5605.51,4538.77) v4(5605.51,4583.68)
  MidLayer3 w30: v4(5605.51,4538.77) v4(5605.51,4583.68)
  Bottom Layer w5: R140.1@5570.46,4419.21 5605.51,4454.26 v4@5605.51,4528.27
  Bottom Layer w50: v4@5605.51,4528.27 J15.11@5605.51,4738.98
EXTCTRL#.CS2_N: J15.12 R138.1 | length 874.8
  Top Layer w30: v4(5605.51,4994.27) v4(5605.51,5039.19)
  MidLayer1 w30: v4(5605.51,4994.27) v4(5605.51,5039.19)
  MidLayer2 w30: v4(5605.51,4994.27) v4(5605.51,5039.19)
  MidLayer4 w30: v4(5605.51,4994.27) v4(5605.51,5039.19)
  MidLayer3 w30: v4(5605.51,4994.27) v4(5605.51,5039.19)
  Bottom Layer w7.87: J15.12@5605.51,4838.98 5653.13,4791.36 R138.1@5653.13,4419.21
  Bottom Layer w50: J15.12@5605.51,4838.98 v4@5605.51,5049.69
EXTCTRL#.DIN1: J15.13 R139.2 | length 798.3
  Top Layer w30: v4(5505.51,4538.77) v4(5505.51,4583.68)
  MidLayer1 w30: v4(5505.51,4538.77) v4(5505.51,4583.68)
  MidLayer2 w30: v4(5505.51,4538.77) v4(5505.51,4583.68)
  MidLayer4 w30: v4(5505.51,4538.77) v4(5505.51,4583.68)
  MidLayer3 w30: v4(5505.51,4538.77) v4(5505.51,4583.68)
  Bottom Layer w5: R139.2@5401.17,4419.21 5505.51,4523.56 J15.13@5505.51,4738.98
  Bottom Layer w50: v4@5505.51,4528.27 J15.13@5505.51,4738.98
EXTCTRL#.DIN2: J15.9 R320.1 | length 1134.9
  Top Layer w30: v4(5705.51,4538.77) v4(5705.51,4583.68)
  MidLayer1 w30: v4(5705.51,4538.77) v4(5705.51,4583.68)
  MidLayer2 w5: v2(5232,4529) 5345,4529 5367,4551 5367,4624 5381,4638 5651.19,4638 v4(5705.51,4583.68)
  MidLayer2 w30: v4(5705.51,4538.77) v4(5705.51,4583.68)
  MidLayer4 w30: v4(5705.51,4538.77) v4(5705.51,4583.68)
  MidLayer3 w30: v4(5705.51,4538.77) v4(5705.51,4583.68)
  Bottom Layer w5: R320.1@5231.88,4419.21 5231.88,4528.88 v2(5232,4529) v2@5237,4532
  Bottom Layer w50: v4@5705.51,4528.27 J15.9@5705.51,4738.98
EXTCTRL#.SCK1: J15.15 R141.2 | length 705.1
  Top Layer w30: v4(5405.51,4538.77) v4(5405.51,4583.68)
  MidLayer1 w30: v4(5405.51,4538.77) v4(5405.51,4583.68)
  MidLayer2 w30: v4(5405.51,4538.77) v4(5405.51,4583.68)
  MidLayer4 w30: v4(5405.51,4538.77) v4(5405.51,4583.68)
  MidLayer3 w30: v4(5405.51,4538.77) v4(5405.51,4583.68)
  Bottom Layer w5: v4@5405.51,4528.27 5405.51,4484.91 5364.3,4443.7 5364.3,4408.8 5375.7,4397.4 5430.8,4397.4 5452.61,4419.21 R141.2@5483.84,4419.21
  Bottom Layer w50: v4@5405.51,4528.27 J15.15@5405.51,4738.98
EXTCTRL#.SCK2: J15.10 R189.1 | length 1352.7
  Top Layer w30: v4(5705.51,4994.27) v4(5705.51,5039.19)
  MidLayer1 w30: v4(5705.51,4994.27) v4(5705.51,5039.19)
  MidLayer2 w5: v2(5314.55,4610.45) 5359.1,4655 5667,4655 5705.51,4693.51 v4(5705.51,4994.27)
  MidLayer2 w30: v4(5705.51,4994.27) v4(5705.51,5039.19)
  MidLayer4 w30: v4(5705.51,4994.27) v4(5705.51,5039.19)
  MidLayer3 w30: v4(5705.51,4994.27) v4(5705.51,5039.19)
  Bottom Layer w5: R189.1@5314.55,4419.21 v2(5314.55,4610.45)
  Bottom Layer w50: J15.10@5705.51,4838.98 v4@5705.51,5049.69
EXTCTRL.CS1_N: R140.2 U5.F19 | length 6133.7
  Top Layer w7.87: U5.F19@10204.72,3740.16 v1(10224.41,3759.84)
  MidLayer4 w5: v1(10224.41,3759.84) 10244.09,3779.53 10244.09,3905.51 10267.72,3929.13 10362.2,3929.13 10409.45,3976.38 10409.45,4165.35 v1(10484.25,4240.16)
  MidLayer3 w7.87: v1(7748.03,4555.12) 7748.03,4523.62 7830.71,4440.94 10015.75,4440.94 10095.55,4520.75 10479.25,4520.75 10507.87,4492.13 10507.87,4263.78 v1(10484.25,4240.16)
  Bottom Layer w7.87: R140.2@5572.04,4376.85 5572.04,4378.43 R140.2@5570.46,4376.85 5570.46,4341.54 5581.29,4330.71 7551.18,4330.71 7748.03,4527.56 v1(7748.03,4555.12)
EXTCTRL.CS2_N: R138.2 U5.F18 | length 6088.1
  Top Layer w7.87: U5.F18@10165.35,3740.16 v1(10185.04,3759.84)
  MidLayer4 w5: v1(10185.04,3759.84) 10204.72,3779.53 10204.72,3909.45 10234.41,3939.13 10358.06,3939.13 10397.64,3978.71 10397.64,4185.04 v1(10484.25,4271.65)
  MidLayer3 w7.87: v1(7724.41,4590.55) 7724.41,4519.69 7818.9,4425.2 10023.62,4425.2 10106.3,4507.87 10452.76,4507.87 10484.25,4476.38 v1(10484.25,4271.65)
  Bottom Layer w7.87: R138.2@5653.13,4376.85 5653.13,4362.61 5669.29,4346.46 7543.31,4346.46 7724.41,4527.56 v1(7724.41,4590.55)
EXTCTRL.DIN1: R139.1 U5.F21 | length 6332.8
  Top Layer w7.87: U5.F21@10283.46,3740.16 v1(10303.15,3759.84)
  MidLayer4 w5: v1(10303.15,3759.84) 10322.83,3779.53 10322.83,3893.7 10334.65,3905.51 10377.95,3905.51 10484.25,4011.81 v1(10484.25,4173.23)
  MidLayer3 w7.87: v1(7795.28,4555.12) 7795.28,4531.5 7854.33,4472.44 10000,4472.44 10074.06,4546.5 10516.5,4546.5 10547.24,4515.75 10547.24,4236.22 v1(10484.25,4173.23)
  Bottom Layer w7.87: R139.1@5401.17,4376.85 5401.17,4327.18 5429.13,4299.21 7566.93,4299.21 7795.28,4527.56 v1(7795.28,4555.12) ; R139.1@5403.54,4376.85 R139.1@5403.54,4378.43
EXTCTRL.DIN2: R320.2 U5.F16 | length 7090.2
  Top Layer w7.87: U5.F16@10086.61,3740.16 v1(10106.3,3759.84)
  MidLayer4 w5: v2(5163,4544) 5203,4544 5228,4569 v2(5228,4969) ; v1(10106.3,3759.84) 10086.6,3779.54 10086.6,3959.2 10109.3,3981.9 10109.3,4001 10128.8,4020.5 10177.5,4020.5 10311,4154 10311,4241 10376,4306 v9@10389,4306
  MidLayer3 w5: v2(5228,4969) 5272,4969 5294,4947 5530.86,4947 5551,4967.14 5551,5051 5616,5116 6214.66,5116 6765.16,4565.5 6847.16,4565.5 7030.16,4382.5 9297.86,4382.5 9303.86,4388.5 9448.7,4388.5 9456.74,4380.45 10230.83,4380.45 10308.28,4303 v9(10401,4303)
  Bottom Layer w5: v2(5163,4544) 5163,4390 5176.15,4376.85 R320.2@5231.88,4376.85
EXTCTRL.SCK1: R141.1 U5.F20 | length 6316.3
  Top Layer w7.87: U5.F20@10244.09,3740.16 v1(10263.78,3759.84)
  MidLayer4 w5: v1(10263.78,3759.84) 10283.46,3779.53 10283.46,3901.57 10299.21,3917.32 10370.08,3917.32 10472.44,4019.68 10472.44,4114.17 10464.57,4122.05 10464.57,4188.98 v1(10484.25,4208.66)
  MidLayer3 w7.87: v1(7771.65,4590.55) 7771.65,4527.56 7842.52,4456.69 10007.87,4456.69 10084.8,4533.62 10501.81,4533.62 10523.62,4511.81 10523.62,4248.03 v1(10484.25,4208.66)
  Bottom Layer w7.87: R141.1@5485.42,4376.85 5485.42,4378.43 R141.1@5483.84,4376.85 5483.84,4330.16 5499.04,4314.96 7559.06,4314.96 7771.65,4527.56 v1(7771.65,4590.55)
EXTCTRL.SCK2: R189.2 U5.F17 | length 6933.6
  Top Layer w7.87: U5.F17@10125.98,3740.16 v1(10145.67,3759.84)
  MidLayer4 w5: v2(5268,4937) 5268,4585 5281,4572 v2(5341,4572) ; v1(10145.67,3759.84) 10126,3779.51 10126,3953 10326,4153 10326,4239 10351,4264 v9@10393,4264
  MidLayer3 w5: v2(5268,4937) 5535,4937 5561,4963 5561,5046.86 5620.14,5106 6210.52,5106 6761.02,4555.5 6843.02,4555.5 7026.02,4372.5 9302,4372.5 9308,4378.5 9444.55,4378.5 9452.6,4370.45 10226.69,4370.45 10334.14,4263 v9(10404,4263)
  Bottom Layer w5: R189.2@5314.55,4376.85 5335.85,4376.85 5341,4382 v2(5341,4572)
FBK: R67.1 R68.2 U12.8 | length 499.6
  Bottom Layer w7.87: R68.2@4090.68,1647.63 4090.32,1647.27 R67.1@4043.68,1647.27 4043.68,1543.45 4098.68,1488.45 4098.68,1358.45 4135.68,1321.45 U12.8@4224.18,1321.45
